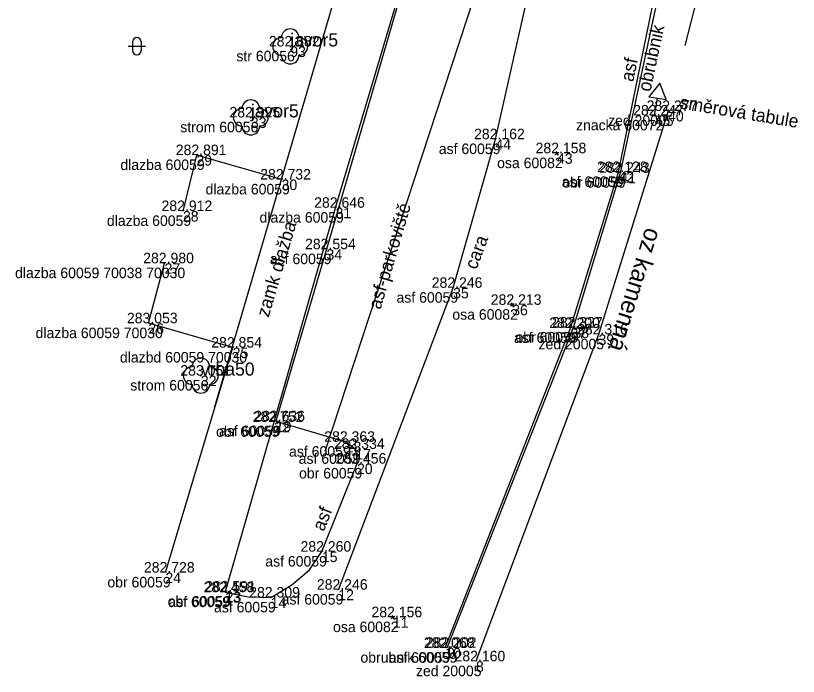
# Model space of a CAD drawing. Extents: x -728659 to -728362, y -1073110 to -1072943.
# Drawn here: x -728543.14 to -728498.39, y -1073109.6 to -1073071.85 of the extents above; entities that cross this region are included whole.
import ezdxf

# ---------------------------------------------------------------- set-up
doc = ezdxf.new("R2010")
doc.units = 0
for name, color, linetype in [('Vrstva 13', 7, 'Continuous'), ('Vrstva 49', 7, 'Continuous'), ('Vrstva 50', 7, 'Continuous'), ('Vrstva 51', 7, 'Continuous'), ('Vrstva 55', 7, 'Continuous'), ('Vrstva 58', 7, 'Continuous'), ('Vrstva 60', 7, 'Continuous'), ('Vrstva 61', 7, 'Continuous'), ('Vrstva 62', 7, 'Continuous'), ('Vrstva 63', 7, 'Continuous')]:
    doc.layers.add(name, color=color, linetype=linetype)

msp = doc.modelspace()

# ---------------------------------------------------------------- linework, layer by layer
at = {"layer": 'Vrstva 13'}
msp.add_lwpolyline([(-728505.84, -1073077.298), (-728509.816, -1073090.065), (-728516.822, -1073108.739)], dxfattribs=at)
at = {"layer": 'Vrstva 49'}
for p, q in [((-728512.255, -1073079.609), (-728512.121, -1073079.821)), ((-728512.294, -1073079.782), (-728512.082, -1073079.648)), ((-728514.856, -1073088.44), (-728514.644, -1073088.306)), ((-728514.817, -1073088.267), (-728514.683, -1073088.479)), ((-728521.676, -1073106.288), (-728521.464, -1073106.154)), ((-728521.637, -1073106.115), (-728521.503, -1073106.327))]:
    msp.add_line(p, q, dxfattribs=at)
at = {"layer": 'Vrstva 50'}
for p, q in [((-728527.471, -1073073.614), (-728527.4, -1073073.614)), ((-728529.723, -1073077.667), (-728529.652, -1073077.667)), ((-728532.581, -1073092.419), (-728532.51, -1073092.419))]:
    msp.add_line(p, q, dxfattribs=at)
for centre, start, end in [((-728527.441, -1073073.113), 0, 180), ((-728527.941, -1073073.613), 90, 270), ((-728526.941, -1073073.613), 270, 90), ((-728527.441, -1073074.113), 180, 0), ((-728529.693, -1073077.166), 0, 180), ((-728530.193, -1073077.666), 90, 270), ((-728529.193, -1073077.666), 270, 90), ((-728529.693, -1073078.166), 180, 0), ((-728532.551, -1073091.918), 0, 180), ((-728533.051, -1073092.418), 90, 270), ((-728532.051, -1073092.418), 270, 90), ((-728532.551, -1073092.918), 180, 0)]:
    msp.add_arc(centre, 0.5, start, end, dxfattribs=at)
at = {"layer": 'Vrstva 51'}
msp.add_line((-728506.858, -1073077.515), (-728506.364, -1073077.597), dxfattribs=at)
for points in [[(-728531.131, -1073104.759), (-728528.363, -1073095.064), (-728524.847, -1073082.829), (-728520.445, -1073068.019), (-728519.555, -1073066.763), (-728518.532, -1073066.599), (-728513.679, -1073067.545)], [(-728513.171, -1073067.654), (-728514.129, -1073069.149), (-728515.701, -1073069.511), (-728520.385, -1073068.108), (-728525.367, -1073085.199), (-728528.271, -1073095.025), (-728524.268, -1073096.199), (-728523.716, -1073096.605), (-728523.622, -1073097.442)], [(-728524.69, -1073104.648), (-728518.127, -1073087.402), (-728515.708, -1073078.91), (-728513.171, -1073067.654)], [(-728518.577, -1073107.972), (-728511.413, -1073089.698), (-728508.676, -1073080.788), (-728506.273, -1073069.065)], [(-728518.469, -1073107.966), (-728511.248, -1073089.672), (-728508.568, -1073080.832), (-728506.346, -1073070.488)], [(-728506.611, -1073077.556), (-728506.447, -1073076.57), (-728505.954, -1073076.652), (-728506.304, -1073075.706), (-728506.94, -1073076.488), (-728506.447, -1073076.57)], [(-728527.933, -1073081.215), (-728532.804, -1073079.821), (-728533.573, -1073083.015)], [(-728534.577, -1073103.667), (-728530.73, -1073090.819), (-728535.551, -1073089.428), (-728534.621, -1073085.999)], [(-728531.165, -1073104.792), (-728529.851, -1073105.049), (-728528.558, -1073105.095), (-728527.351, -1073104.362), (-728526.348, -1073103.519), (-728525.628, -1073102.474), (-728523.622, -1073097.442)]]:
    msp.add_lwpolyline(points, dxfattribs=at)
at = {"layer": 'Vrstva 55'}
for p, q in [((-728525.44, -1073096.73), (-728510.66, -1073051.71)), ((-728504.87, -1073073.55), (-728499.33, -1073052.26)), ((-728531.77, -1073094.25), (-728523.51, -1073066.11))]:
    msp.add_line(p, q, dxfattribs=at)
at = {"layer": 'Vrstva 58'}
for p, q in [((-728536.462, -1073073.346), (-728536.462, -1073073.846)), ((-728535.962, -1073073.346), (-728535.962, -1073073.846)), ((-728536.712, -1073073.596), (-728535.712, -1073073.596))]:
    msp.add_line(p, q, dxfattribs=at)
for centre, start, end in [((-728536.212, -1073073.346), 0, 180), ((-728536.212, -1073073.846), 180, 0)]:
    msp.add_arc(centre, 0.25, start, end, dxfattribs=at)
at = {"layer": 'Vrstva 60'}
for p, q in [((-728527.436, -1073073.614), (-728527.436, -1073073.614)), ((-728505.84, -1073077.298), (-728505.84, -1073077.298)), ((-728529.687, -1073077.667), (-728529.687, -1073077.667)), ((-728506.611, -1073077.556), (-728506.611, -1073077.556)), ((-728515.708, -1073078.91), (-728515.708, -1073078.91)), ((-728532.804, -1073079.821), (-728532.804, -1073079.821)), ((-728512.188, -1073079.715), (-728512.188, -1073079.715)), ((-728508.676, -1073080.788), (-728508.676, -1073080.788)), ((-728508.568, -1073080.832), (-728508.568, -1073080.832)), ((-728527.933, -1073081.215), (-728527.933, -1073081.215)), ((-728533.573, -1073083.015), (-728533.573, -1073083.015)), ((-728524.847, -1073082.829), (-728524.847, -1073082.829)), ((-728525.367, -1073085.199), (-728525.367, -1073085.199)), ((-728534.621, -1073085.999), (-728534.621, -1073085.999)), ((-728518.127, -1073087.402), (-728518.127, -1073087.402)), ((-728514.75, -1073088.373), (-728514.75, -1073088.373)), ((-728535.551, -1073089.428), (-728535.551, -1073089.428)), ((-728511.413, -1073089.698), (-728511.413, -1073089.698)), ((-728511.248, -1073089.672), (-728511.248, -1073089.672)), ((-728509.816, -1073090.065), (-728509.816, -1073090.065)), ((-728530.73, -1073090.819), (-728530.73, -1073090.819)), ((-728532.545, -1073092.419), (-728532.545, -1073092.419)), ((-728528.363, -1073095.064), (-728528.363, -1073095.064)), ((-728528.271, -1073095.025), (-728528.271, -1073095.025)), ((-728524.268, -1073096.199), (-728524.268, -1073096.199)), ((-728523.716, -1073096.605), (-728523.716, -1073096.605)), ((-728523.622, -1073097.442), (-728523.622, -1073097.442)), ((-728525.628, -1073102.474), (-728525.628, -1073102.474)), ((-728534.577, -1073103.667), (-728534.577, -1073103.667)), ((-728524.69, -1073104.648), (-728524.69, -1073104.648)), ((-728531.165, -1073104.792), (-728531.165, -1073104.792)), ((-728531.131, -1073104.759), (-728531.131, -1073104.759)), ((-728528.558, -1073105.095), (-728528.558, -1073105.095)), ((-728521.57, -1073106.221), (-728521.57, -1073106.221)), ((-728518.577, -1073107.972), (-728518.577, -1073107.972)), ((-728518.469, -1073107.966), (-728518.469, -1073107.966)), ((-728516.822, -1073108.739), (-728516.822, -1073108.739))]:
    msp.add_line(p, q, dxfattribs=at)

# ---------------------------------------------------------------- texts
at = {"layer": 'Vrstva 13'}
msp.add_text('oz kamenná', height=1, rotation=252.702, dxfattribs=at).set_placement((-728507.112, -1073083.905))
at = {"layer": 'Vrstva 51'}
for s, rotation, p in [('obrubnik', 77.8765, (-728506.852, -1073076.234)), ('asf', 78.4159, (-728507.836, -1073075.667)), ('asf-parkoviště', 73.7487, (-728522.281, -1073088.676)), ('zamk dlažba', 73.4464, (-728528.679, -1073089.127)), ('cara', 69.1656, (-728516.802, -1073086.402)), ('asf', 68.2654, (-728525.52, -1073101.354))]:
    msp.add_text(s, height=0.75, rotation=rotation, dxfattribs=at).set_placement(p)
at = {"layer": 'Vrstva 60'}
for s, p in [('93', (-728527.436, -1073074.214)), ('40', (-728505.84, -1073077.898)), ('33', (-728529.687, -1073078.267)), ('45', (-728506.611, -1073078.156)), ('44', (-728515.708, -1073079.51)), ('29', (-728532.804, -1073080.421)), ('43', (-728512.188, -1073080.315)), ('42', (-728508.676, -1073081.388)), ('41', (-728508.568, -1073081.432)), ('30', (-728527.933, -1073081.815)), ('28', (-728533.573, -1073083.615)), ('31', (-728524.847, -1073083.429)), ('34', (-728525.367, -1073085.799)), ('27', (-728534.621, -1073086.599)), ('35', (-728518.127, -1073088.002)), ('36', (-728514.75, -1073088.973)), ('26', (-728535.551, -1073090.028)), ('37', (-728511.413, -1073090.298)), ('38', (-728511.248, -1073090.272)), ('39', (-728509.816, -1073090.665)), ('25', (-728530.73, -1073091.419)), ('32', (-728532.545, -1073093.019)), ('22', (-728528.363, -1073095.664)), ('19', (-728528.271, -1073095.625)), ('18', (-728524.268, -1073096.799)), ('17', (-728523.716, -1073097.205)), ('20', (-728523.622, -1073098.042)), ('15', (-728525.628, -1073103.074)), ('24', (-728534.577, -1073104.267)), ('12', (-728524.69, -1073105.248)), ('13', (-728531.165, -1073105.392)), ('23', (-728531.131, -1073105.359)), ('14', (-728528.558, -1073105.695)), ('11', (-728521.57, -1073106.821)), ('10', (-728518.577, -1073108.572)), ('9', (-728518.469, -1073108.566)), ('8', (-728516.822, -1073109.339))]:
    msp.add_text(s, height=0.6, dxfattribs=at).set_placement(p)
at = {"layer": 'Vrstva 61'}
for s, p in [('282.682', (-728528.66, -1073073.614)), ('282.277', (-728507.066, -1073077.298)), ('282.925', (-728530.915, -1073077.667)), ('282.247', (-728507.837, -1073077.556)), ('282.162', (-728516.932, -1073078.91)), ('282.158', (-728513.415, -1073079.715)), ('282.891', (-728533.983, -1073079.821)), ('282.128', (-728509.903, -1073080.788)), ('282.243', (-728509.794, -1073080.832)), ('282.732', (-728529.157, -1073081.215)), ('282.646', (-728526.073, -1073082.829)), ('282.912', (-728534.797, -1073083.015)), ('282.554', (-728526.592, -1073085.199)), ('282.980', (-728535.846, -1073085.999)), ('282.246', (-728519.353, -1073087.402)), ('282.213', (-728515.976, -1073088.373)), ('283.053', (-728536.777, -1073089.428)), ('282.200', (-728512.638, -1073089.698)), ('282.327', (-728512.474, -1073089.672)), ('282.316', (-728511.042, -1073090.065)), ('282.854', (-728531.955, -1073090.819)), ('283.051', (-728533.724, -1073092.419)), ('282.752', (-728529.587, -1073095.064)), ('282.636', (-728529.497, -1073095.025)), ('282.363', (-728525.494, -1073096.199)), ('282.334', (-728524.941, -1073096.605)), ('282.456', (-728524.848, -1073097.442)), ('282.260', (-728526.853, -1073102.474)), ('282.728', (-728535.804, -1073103.667)), ('282.458', (-728532.392, -1073104.792)), ('282.591', (-728532.31, -1073104.759)), ('282.246', (-728525.916, -1073104.648)), ('282.309', (-728529.785, -1073105.095)), ('282.156', (-728522.796, -1073106.221)), ('282.068', (-728519.804, -1073107.972)), ('282.202', (-728519.693, -1073107.966)), ('282.160', (-728518.047, -1073108.739))]:
    msp.add_text(s, height=0.6, dxfattribs=at).set_placement(p)
at = {"layer": 'Vrstva 62'}
for s, p in [('str 60056', (-728530.52, -1073074.464)), ('znacka 60072', (-728511.105, -1073078.406)), ('zed 20005', (-728509.272, -1073078.148)), ('strom 60056', (-728533.726, -1073078.517)), ('asf 60059', (-728518.947, -1073079.76)), ('dlazba 60059', (-728537.151, -1073080.671)), ('osa 60082', (-728515.612, -1073080.565)), ('asf 60059', (-728511.915, -1073081.638)), ('obr 60059', (-728511.883, -1073081.682)), ('dlazba 60059', (-728532.28, -1073082.065)), ('dlazba 60059', (-728529.194, -1073083.679)), ('dlazba 60059', (-728537.92, -1073083.865)), ('asf 60059', (-728528.606, -1073086.049)), ('dlazba 60059 70038 70030', (-728543.17, -1073086.849)), ('asf 60059', (-728521.366, -1073088.252)), ('osa 60082', (-728518.174, -1073089.223)), ('dlazba 60059 70030', (-728541.997, -1073090.278)), ('asf 60059', (-728514.652, -1073090.548)), ('obr 60059', (-728514.563, -1073090.522)), ('zed 20005', (-728513.248, -1073090.915)), ('dlazbd 60059 70030', (-728537.176, -1073091.669)), ('strom 60056', (-728536.584, -1073093.269)), ('obr 60059', (-728531.678, -1073095.914)), ('asf 60059', (-728531.51, -1073095.875)), ('asf 60059', (-728527.507, -1073097.049)), ('asf 60059', (-728526.955, -1073097.455)), ('obr 60059', (-728526.937, -1073098.292)), ('asf 60059', (-728528.867, -1073103.324)), ('obr 60059', (-728537.892, -1073104.517)), ('obr 60059', (-728534.446, -1073105.609)), ('asf 60059', (-728534.404, -1073105.642)), ('asf 60059', (-728527.929, -1073105.498)), ('asf 60059', (-728531.797, -1073105.945)), ('osa 60082', (-728524.994, -1073107.071)), ('obrubnik 60059', (-728523.427, -1073108.816)), ('asf 60059', (-728521.816, -1073108.822)), ('zed 20005', (-728520.254, -1073109.589))]:
    msp.add_text(s, height=0.6, dxfattribs=at).set_placement(p)
at = {"layer": 'Vrstva 63'}
for s, p in [('javor5', (-728527.436, -1073073.614)), ('javor5', (-728529.687, -1073077.667)), ('vrba50', (-728532.545, -1073092.419))]:
    msp.add_text(s, height=0.75, dxfattribs=at).set_placement(p)
msp.add_text('směrová tabule', height=0.75, rotation=350.5614, dxfattribs=at).set_placement((-728505.21, -1073077.147))

doc.saveas('drawing.dxf')
